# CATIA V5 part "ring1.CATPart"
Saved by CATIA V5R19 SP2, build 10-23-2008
Part number: ring1
Bounding box of the stored display mesh (mm): x 1196.495 to 1608.814, y 572 to 1057, z 2.015 to 414.335
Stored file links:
  C:\BEHROOZ\catia learning\tarh haye mashin\hb\ring1.CATPart
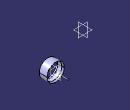
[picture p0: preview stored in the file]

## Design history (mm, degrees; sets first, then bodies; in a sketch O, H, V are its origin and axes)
Body1 (main body)
  DatumCurve1
  DatumCurve2
  Sketch1 on zx-plane, origin (0, 0, 0), H (-1, 0, 0), V (0, 0, 1)
    circle A1 centre (-1402.6545, 208.175) radius 206.1598
    circle A2 centre (-1402.6545, 208.175) radius 191.1068
  Pad1: profile Sketch1, direction (0, 1, 0), length 756, opposite side length -572
  Fillet1: radius 75, on edge [end face of Pad1 | face of Pad1 from Sketch1.A2]; edge [face of Pad1 from Sketch1.A2 | start face of Pad1]
  Point1: type Center, Curve edge [face of Pad1 from Sketch1.A1 | face of Fillet1]
  Plane1: type OffsetPt, RefPlane zx-plane, RefPoint Point1
  Line1: type PtDir, RefPoint Point1, Direction Plane1, Start 0, End 301
  Plane2: type OffsetPt, RefPlane yz-plane, RefPoint Point1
